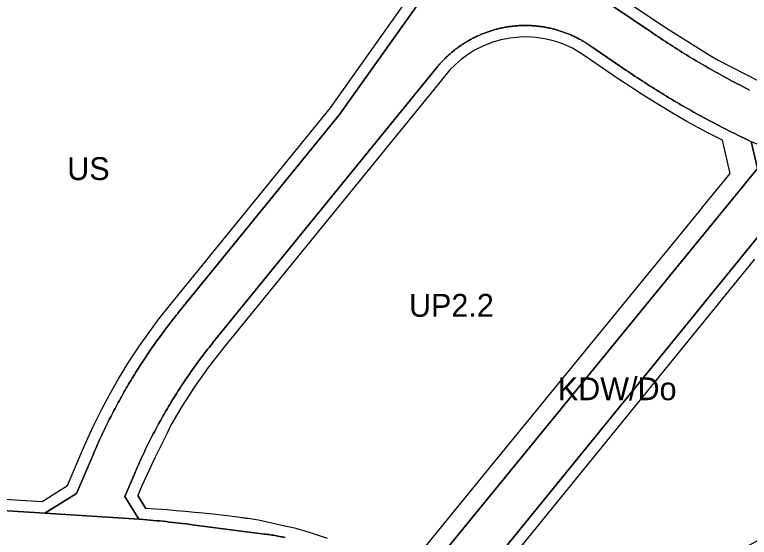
# Model space of a CAD drawing. Extents: x -297746 to -295403, y 27112 to 28877.
# Drawn here: x -296302 to -295980.2, y 28247.4 to 28476.1 of the extents above; entities that cross this region are included whole.
import ezdxf

# ---------------------------------------------------------------- set-up
doc = ezdxf.new("R2010")
doc.units = 0
for name, color, linetype in [('linie_rozgraniczajace', 7, 'Continuous'), ('linie_zabudowy_nieprzekraczalne', 7, 'Continuous'), ('oznaczenia_przeznaczen', 7, 'Continuous')]:
    doc.layers.add(name, color=color, linetype=linetype)

msp = doc.modelspace()

# ---------------------------------------------------------------- linework, layer by layer
at = {"layer": 'linie_rozgraniczajace'}
for points in [[(-295964.466, 28672.993), (-296078.491, 28512.337), (-296077.256, 28505.44), (-296048.43, 28485.757), (-296023.068, 28468.439), (-296022.062, 28467.755), (-296021.054, 28467.074), (-296020.044, 28466.396), (-296019.031, 28465.722), (-296018.016, 28465.051), (-296016.999, 28464.383), (-296015.98, 28463.719), (-296014.959, 28463.058), (-296013.936, 28462.4), (-296012.91, 28461.746), (-296011.882, 28461.095)], [(-296247.672, 28255.329), (-296288.797, 28257.976), (-296274.91, 28266.565), (-296267.737, 28283.472), (-296267.345, 28284.392), (-296266.941, 28285.329), (-296266.533, 28286.263), (-296266.122, 28287.197), (-296265.708, 28288.128), (-296265.289, 28289.058), (-296264.867, 28289.987), (-296264.442, 28290.913), (-296264.012, 28291.839), (-296263.579, 28292.762), (-296263.143, 28293.684), (-296262.703, 28294.603), (-296262.259, 28295.522), (-296261.811, 28296.438), (-296261.361, 28297.353), (-296260.906, 28298.266), (-296260.448, 28299.177), (-296259.986, 28300.086), (-296259.521, 28300.994), (-296259.052, 28301.899), (-296258.58, 28302.803), (-296258.104, 28303.705), (-296257.625, 28304.605), (-296257.142, 28305.503), (-296256.655, 28306.4), (-296256.165, 28307.294), (-296255.672, 28308.186), (-296255.175, 28309.077), (-296254.674, 28309.966), (-296254.17, 28310.852), (-296253.663, 28311.737), (-296253.152, 28312.619), (-296252.638, 28313.5), (-296252.12, 28314.378), (-296251.599, 28315.255), (-296251.074, 28316.129), (-296250.546, 28317.002), (-296250.014, 28317.872), (-296249.479, 28318.74), (-296248.941, 28319.607), (-296248.399, 28320.471), (-296247.854, 28321.333), (-296247.306, 28322.192), (-296246.754, 28323.05), (-296246.199, 28323.905), (-296245.64, 28324.759), (-296245.078, 28325.61), (-296244.513, 28326.458), (-296243.944, 28327.305), (-296243.372, 28328.149), (-296242.797, 28328.991), (-296242.219, 28329.831), (-296241.637, 28330.669), (-296241.052, 28331.504), (-296240.464, 28332.337), (-296239.872, 28333.168), (-296239.277, 28333.996), (-296238.679, 28334.822), (-296238.078, 28335.646), (-296237.473, 28336.467), (-296236.865, 28337.286), (-296236.255, 28338.103), (-296235.64, 28338.917), (-296235.023, 28339.728), (-296234.402, 28340.538), (-296233.779, 28341.345), (-296233.152, 28342.149), (-296232.522, 28342.951), (-296231.889, 28343.75), (-296231.252, 28344.547), (-296230.613, 28345.342), (-296229.97, 28346.134), (-296159.711, 28432.386), (-296112.877, 28498.424)], [(-296112.877, 28498.424), (-296159.711, 28432.386), (-296229.97, 28346.134), (-296230.613, 28345.342), (-296231.252, 28344.547), (-296231.889, 28343.75), (-296232.522, 28342.951), (-296233.152, 28342.149), (-296233.779, 28341.345), (-296234.402, 28340.538), (-296235.023, 28339.728), (-296235.64, 28338.917), (-296236.255, 28338.103), (-296236.865, 28337.286), (-296237.473, 28336.467), (-296238.078, 28335.646), (-296238.679, 28334.822), (-296239.277, 28333.996), (-296239.872, 28333.168), (-296240.464, 28332.337), (-296241.052, 28331.504), (-296241.637, 28330.669), (-296242.219, 28329.831), (-296242.797, 28328.991), (-296243.372, 28328.149), (-296243.944, 28327.305), (-296244.513, 28326.458), (-296245.078, 28325.61), (-296245.64, 28324.759), (-296246.199, 28323.905), (-296246.754, 28323.05), (-296247.306, 28322.192), (-296247.854, 28321.333), (-296248.399, 28320.471), (-296248.941, 28319.607), (-296249.479, 28318.74), (-296250.014, 28317.872), (-296250.546, 28317.002), (-296251.074, 28316.129), (-296251.599, 28315.255), (-296252.12, 28314.378), (-296252.638, 28313.5), (-296253.152, 28312.619), (-296253.663, 28311.737), (-296254.17, 28310.852), (-296254.674, 28309.966), (-296255.175, 28309.077), (-296255.672, 28308.186), (-296256.165, 28307.294), (-296256.655, 28306.4), (-296257.142, 28305.503), (-296257.625, 28304.605), (-296258.104, 28303.705), (-296258.58, 28302.803), (-296259.052, 28301.899), (-296259.521, 28300.994), (-296259.986, 28300.086), (-296260.448, 28299.177), (-296260.906, 28298.266), (-296261.361, 28297.353), (-296261.811, 28296.438), (-296262.259, 28295.522), (-296262.703, 28294.603), (-296263.143, 28293.684), (-296263.579, 28292.762), (-296264.012, 28291.839), (-296264.442, 28290.913), (-296264.867, 28289.987), (-296265.289, 28289.058), (-296265.708, 28288.128), (-296266.122, 28287.197), (-296266.533, 28286.263), (-296266.941, 28285.329), (-296267.345, 28284.392), (-296267.737, 28283.472), (-296274.91, 28266.565), (-296288.797, 28257.976)], [(-296288.797, 28257.976), (-296400.521, 28264.886), (-296431.166, 28266.781), (-296434.768, 28272.351), (-296432.067, 28282.612), (-296419.113, 28316.011), (-296378.717, 28384.494), (-296338.263, 28452.547), (-296327.479, 28466.037), (-296306.95, 28488.333)], [(-295980.107, 28443.17), (-295981.194, 28443.717), (-295982.279, 28444.267), (-295983.363, 28444.821), (-295984.444, 28445.378), (-295985.524, 28445.939), (-295986.601, 28446.503), (-295987.677, 28447.071), (-295988.751, 28447.642), (-295989.823, 28448.217), (-295990.894, 28448.796), (-295991.962, 28449.378), (-295993.028, 28449.963), (-295994.093, 28450.552), (-295995.155, 28451.145), (-295996.216, 28451.741), (-295997.274, 28452.34), (-295998.331, 28452.943), (-295999.386, 28453.55), (-296000.438, 28454.159), (-296001.489, 28454.773), (-296002.538, 28455.39), (-296003.584, 28456.01), (-296004.629, 28456.633), (-296005.671, 28457.261), (-296006.712, 28457.891), (-296007.75, 28458.525), (-296008.786, 28459.162), (-296009.82, 28459.803), (-296010.852, 28460.447), (-296011.882, 28461.095), (-296012.91, 28461.746), (-296013.936, 28462.4), (-296014.959, 28463.058), (-296015.98, 28463.719), (-296016.999, 28464.383), (-296018.016, 28465.051), (-296019.031, 28465.722), (-296020.044, 28466.396), (-296021.054, 28467.074), (-296022.062, 28467.755), (-296023.068, 28468.439), (-296048.43, 28485.757)], [(-296079.255, 28471.419), (-296079.702, 28471.409), (-296080.149, 28471.395), (-296080.596, 28471.376), (-296081.043, 28471.354), (-296081.489, 28471.328), (-296081.935, 28471.298), (-296082.381, 28471.264), (-296082.827, 28471.226), (-296083.272, 28471.184), (-296083.717, 28471.138), (-296084.161, 28471.088), (-296084.605, 28471.034), (-296085.049, 28470.976), (-296085.492, 28470.914), (-296085.934, 28470.849), (-296086.376, 28470.779), (-296086.817, 28470.705), (-296087.257, 28470.627), (-296087.697, 28470.546), (-296088.136, 28470.46), (-296088.574, 28470.371), (-296089.012, 28470.277), (-296089.448, 28470.18), (-296089.884, 28470.079), (-296090.318, 28469.974), (-296090.752, 28469.865), (-296091.185, 28469.752), (-296091.617, 28469.635), (-296092.047, 28469.515), (-296092.477, 28469.39), (-296092.905, 28469.262), (-296093.332, 28469.13), (-296093.759, 28468.994), (-296094.183, 28468.854), (-296094.607, 28468.711), (-296095.029, 28468.564), (-296095.45, 28468.413), (-296095.87, 28468.258), (-296096.288, 28468.099), (-296096.705, 28467.937), (-296097.12, 28467.771), (-296097.534, 28467.601), (-296097.946, 28467.428), (-296098.356, 28467.251), (-296098.766, 28467.07), (-296099.173, 28466.886), (-296099.579, 28466.698), (-296099.983, 28466.506), (-296100.385, 28466.311), (-296100.786, 28466.112), (-296101.184, 28465.909), (-296101.581, 28465.703), (-296101.976, 28465.494), (-296102.37, 28465.281), (-296102.761, 28465.064), (-296103.15, 28464.844), (-296103.538, 28464.621), (-296103.923, 28464.394), (-296104.306, 28464.163), (-296104.687, 28463.929), (-296105.067, 28463.692), (-296105.443, 28463.451), (-296105.818, 28463.208), (-296106.191, 28462.96), (-296106.561, 28462.71), (-296106.929, 28462.456), (-296107.295, 28462.198), (-296107.659, 28461.938), (-296108.02, 28461.674), (-296108.379, 28461.407), (-296108.735, 28461.137), (-296109.089, 28460.864), (-296109.44, 28460.587), (-296109.789, 28460.308), (-296110.136, 28460.025), (-296110.48, 28459.739), (-296110.821, 28459.45), (-296111.16, 28459.158), (-296111.496, 28458.863), (-296111.83, 28458.565), (-296112.161, 28458.264), (-296112.489, 28457.96), (-296112.814, 28457.654), (-296113.137, 28457.344), (-296113.457, 28457.031), (-296113.774, 28456.716), (-296114.088, 28456.398), (-296114.399, 28456.077), (-296114.708, 28455.753), (-296115.013, 28455.426), (-296115.316, 28455.097), (-296115.616, 28454.765), (-296115.912, 28454.431), (-296116.206, 28454.093), (-296116.497, 28453.754), (-296116.784, 28453.411), (-296117.069, 28453.066), (-296117.118, 28453.005), (-296214.464, 28333.502)], [(-296111.83, 28458.565), (-296111.496, 28458.863), (-296111.16, 28459.158), (-296110.821, 28459.45), (-296110.48, 28459.739), (-296110.136, 28460.025), (-296109.789, 28460.308), (-296109.44, 28460.587), (-296109.089, 28460.864), (-296108.735, 28461.137), (-296108.379, 28461.407), (-296108.02, 28461.674), (-296107.659, 28461.938), (-296107.295, 28462.198), (-296106.929, 28462.456), (-296106.561, 28462.71), (-296106.191, 28462.96), (-296105.818, 28463.208), (-296105.443, 28463.451), (-296105.067, 28463.692), (-296104.687, 28463.929), (-296104.306, 28464.163), (-296103.923, 28464.394), (-296103.538, 28464.621), (-296103.15, 28464.844), (-296102.761, 28465.064), (-296102.37, 28465.281), (-296101.976, 28465.494), (-296101.581, 28465.703), (-296101.184, 28465.909), (-296100.786, 28466.112), (-296100.385, 28466.311), (-296099.983, 28466.506), (-296099.579, 28466.698), (-296099.173, 28466.886), (-296098.766, 28467.07), (-296098.356, 28467.251), (-296097.946, 28467.428), (-296097.534, 28467.601), (-296097.12, 28467.771), (-296096.705, 28467.937), (-296096.288, 28468.099), (-296095.87, 28468.258), (-296095.45, 28468.413), (-296095.029, 28468.564), (-296094.607, 28468.711), (-296094.183, 28468.854), (-296093.759, 28468.994), (-296093.332, 28469.13), (-296092.905, 28469.262), (-296092.477, 28469.39), (-296092.047, 28469.515), (-296091.617, 28469.635), (-296091.185, 28469.752), (-296090.752, 28469.865), (-296090.318, 28469.974), (-296089.884, 28470.079), (-296089.448, 28470.18), (-296089.012, 28470.277), (-296088.574, 28470.371), (-296088.136, 28470.46), (-296087.697, 28470.546), (-296087.257, 28470.627), (-296086.817, 28470.705), (-296086.376, 28470.779), (-296085.934, 28470.849), (-296085.492, 28470.914), (-296085.049, 28470.976), (-296084.605, 28471.034), (-296084.161, 28471.088), (-296083.717, 28471.138), (-296083.272, 28471.184), (-296082.827, 28471.226), (-296082.381, 28471.264), (-296081.935, 28471.298), (-296081.489, 28471.328), (-296081.043, 28471.354), (-296080.596, 28471.376), (-296080.149, 28471.395), (-296079.702, 28471.409), (-296079.255, 28471.419), (-296078.808, 28471.425), (-296078.361, 28471.427), (-296077.914, 28471.425), (-296077.466, 28471.419), (-296077.019, 28471.409), (-296076.572, 28471.395), (-296076.126, 28471.377), (-296075.679, 28471.355), (-296075.232, 28471.329), (-296074.786, 28471.299), (-296074.34, 28471.266), (-296073.895, 28471.228), (-296073.449, 28471.186), (-296073.005, 28471.14), (-296072.56, 28471.09), (-296072.116, 28471.036), (-296071.673, 28470.979), (-296071.23, 28470.917), (-296070.787, 28470.851)], [(-296003.528, 28432.915), (-296004.619, 28433.522), (-296005.709, 28434.133), (-296006.796, 28434.748), (-296007.882, 28435.365), (-296008.965, 28435.987), (-296010.047, 28436.611), (-296011.126, 28437.24), (-296012.204, 28437.871), (-296013.279, 28438.506), (-296014.353, 28439.145), (-296015.424, 28439.787), (-296016.493, 28440.432), (-296017.561, 28441.081), (-296018.626, 28441.734), (-296019.689, 28442.389), (-296020.75, 28443.048), (-296021.809, 28443.711), (-296022.865, 28444.377), (-296023.92, 28445.046), (-296024.972, 28445.718), (-296026.023, 28446.394), (-296027.071, 28447.074), (-296028.117, 28447.756), (-296029.16, 28448.442), (-296030.202, 28449.132), (-296031.241, 28449.825), (-296032.278, 28450.521), (-296033.313, 28451.22), (-296034.346, 28451.923), (-296050.158, 28462.719), (-296050.528, 28462.97), (-296050.901, 28463.217), (-296051.276, 28463.461), (-296051.653, 28463.701), (-296052.032, 28463.938), (-296052.413, 28464.172), (-296052.796, 28464.402), (-296053.182, 28464.629), (-296053.569, 28464.853), (-296053.959, 28465.072), (-296054.35, 28465.289), (-296054.743, 28465.502), (-296055.138, 28465.711), (-296055.535, 28465.917), (-296055.934, 28466.119), (-296056.335, 28466.318), (-296056.737, 28466.513), (-296057.141, 28466.705), (-296057.547, 28466.893), (-296057.955, 28467.077), (-296058.364, 28467.258), (-296058.775, 28467.435), (-296059.187, 28467.608), (-296059.601, 28467.777), (-296060.016, 28467.943), (-296060.433, 28468.105), (-296060.851, 28468.264), (-296061.271, 28468.418), (-296061.692, 28468.569), (-296062.114, 28468.716), (-296062.537, 28468.86), (-296062.962, 28468.999), (-296063.388, 28469.135), (-296063.816, 28469.267), (-296064.244, 28469.395), (-296064.674, 28469.519), (-296065.105, 28469.64), (-296065.536, 28469.756), (-296065.969, 28469.869), (-296066.403, 28469.978), (-296066.838, 28470.083), (-296067.273, 28470.184), (-296067.71, 28470.281), (-296068.147, 28470.374), (-296068.585, 28470.464), (-296069.024, 28470.549), (-296069.464, 28470.63), (-296069.904, 28470.708), (-296070.346, 28470.782), (-296070.787, 28470.851), (-296071.23, 28470.917), (-296071.673, 28470.979), (-296072.116, 28471.036), (-296072.56, 28471.09), (-296073.005, 28471.14), (-296073.449, 28471.186), (-296073.895, 28471.228), (-296074.34, 28471.266), (-296074.786, 28471.299), (-296075.232, 28471.329), (-296075.679, 28471.355), (-296076.126, 28471.377), (-296076.572, 28471.395), (-296077.019, 28471.409), (-296077.466, 28471.419), (-296077.914, 28471.425), (-296078.361, 28471.427), (-296078.808, 28471.425), (-296079.255, 28471.419)], [(-296070.787, 28470.851), (-296070.346, 28470.782), (-296069.904, 28470.708), (-296069.464, 28470.63), (-296069.024, 28470.549), (-296068.585, 28470.464), (-296068.147, 28470.374), (-296067.71, 28470.281), (-296067.273, 28470.184), (-296066.838, 28470.083), (-296066.403, 28469.978), (-296065.969, 28469.869), (-296065.536, 28469.756), (-296065.105, 28469.64), (-296064.674, 28469.519), (-296064.244, 28469.395), (-296063.816, 28469.267), (-296063.388, 28469.135), (-296062.962, 28468.999), (-296062.537, 28468.86), (-296062.114, 28468.716), (-296061.692, 28468.569), (-296061.271, 28468.418), (-296060.851, 28468.264), (-296060.433, 28468.105), (-296060.016, 28467.943), (-296059.601, 28467.777), (-296059.187, 28467.608), (-296058.775, 28467.435), (-296058.364, 28467.258), (-296057.955, 28467.077), (-296057.547, 28466.893), (-296057.141, 28466.705), (-296056.737, 28466.513), (-296056.335, 28466.318), (-296055.934, 28466.119), (-296055.535, 28465.917), (-296055.138, 28465.711), (-296054.743, 28465.502), (-296054.35, 28465.289), (-296053.959, 28465.072), (-296053.569, 28464.853), (-296053.182, 28464.629), (-296052.796, 28464.402), (-296052.413, 28464.172), (-296052.032, 28463.938), (-296051.653, 28463.701), (-296051.276, 28463.461), (-296050.901, 28463.217), (-296050.528, 28462.97), (-296050.158, 28462.719), (-296034.346, 28451.923), (-296033.313, 28451.22), (-296032.278, 28450.521), (-296031.241, 28449.825), (-296030.202, 28449.132), (-296029.16, 28448.442), (-296028.117, 28447.756), (-296027.071, 28447.074), (-296026.023, 28446.394), (-296024.972, 28445.718), (-296023.92, 28445.046), (-296022.865, 28444.377), (-296021.809, 28443.711), (-296020.75, 28443.048), (-296019.689, 28442.389), (-296018.626, 28441.734), (-296017.561, 28441.081), (-296016.493, 28440.432), (-296015.424, 28439.787), (-296014.353, 28439.145), (-296013.279, 28438.506), (-296012.204, 28437.871), (-296011.126, 28437.24), (-296010.047, 28436.611), (-296008.965, 28435.987), (-296007.882, 28435.365), (-296006.796, 28434.748), (-296005.709, 28434.133), (-296004.619, 28433.522), (-296003.528, 28432.915), (-296002.435, 28432.311), (-296001.339, 28431.711), (-296000.242, 28431.114), (-295999.143, 28430.521), (-295998.042, 28429.931), (-295996.939, 28429.345), (-295995.835, 28428.762), (-295994.728, 28428.183), (-295993.62, 28427.607), (-295992.509, 28427.035), (-295991.397, 28426.466), (-295990.283, 28425.901), (-295989.168, 28425.34), (-295988.05, 28424.782), (-295986.931, 28424.228), (-295985.81, 28423.677), (-295984.687, 28423.13), (-295983.562, 28422.587), (-295982.436, 28422.047)], [(-296011.882, 28461.095), (-296010.852, 28460.447), (-296009.82, 28459.803), (-296008.786, 28459.162), (-296007.75, 28458.525), (-296006.712, 28457.891), (-296005.671, 28457.261), (-296004.629, 28456.633), (-296003.584, 28456.01), (-296002.538, 28455.39), (-296001.489, 28454.773), (-296000.438, 28454.159), (-295999.386, 28453.55), (-295998.331, 28452.943), (-295997.274, 28452.34), (-295996.216, 28451.741), (-295995.155, 28451.145), (-295994.093, 28450.552), (-295993.028, 28449.963), (-295991.962, 28449.378), (-295990.894, 28448.796), (-295989.823, 28448.217), (-295988.751, 28447.642), (-295987.677, 28447.071), (-295986.601, 28446.503), (-295985.524, 28445.939), (-295984.444, 28445.378), (-295983.363, 28444.821), (-295982.279, 28444.267), (-295981.194, 28443.717), (-295980.107, 28443.17)], [(-296237.058, 28254.346), (-296238.479, 28254.491), (-296239.9, 28254.632), (-296241.322, 28254.768), (-296242.744, 28254.901), (-296244.166, 28255.03), (-296245.589, 28255.154), (-296247.012, 28255.275), (-296247.672, 28255.329), (-296253.74, 28265.256), (-296249.325, 28275.661), (-296249.265, 28275.802), (-296248.88, 28276.703), (-296248.491, 28277.603), (-296248.099, 28278.5), (-296247.703, 28279.397), (-296247.303, 28280.291), (-296246.9, 28281.184), (-296246.493, 28282.075), (-296246.082, 28282.965), (-296245.668, 28283.853), (-296245.25, 28284.739), (-296244.828, 28285.623), (-296244.403, 28286.506), (-296243.974, 28287.387), (-296243.542, 28288.266), (-296243.106, 28289.144), (-296242.667, 28290.02), (-296242.224, 28290.893), (-296241.777, 28291.766), (-296241.327, 28292.636), (-296240.873, 28293.504), (-296240.416, 28294.371), (-296239.955, 28295.235), (-296239.491, 28296.098), (-296239.023, 28296.959), (-296238.551, 28297.818), (-296238.076, 28298.675), (-296237.598, 28299.53), (-296237.116, 28300.383), (-296236.631, 28301.234), (-296236.142, 28302.084), (-296235.65, 28302.931), (-296235.154, 28303.776), (-296234.655, 28304.619), (-296234.152, 28305.46), (-296233.646, 28306.299), (-296233.137, 28307.136), (-296232.624, 28307.971), (-296232.108, 28308.803), (-296231.588, 28309.634), (-296231.065, 28310.463), (-296230.539, 28311.289), (-296230.009, 28312.113), (-296229.476, 28312.935), (-296228.939, 28313.755), (-296228.399, 28314.573), (-296227.856, 28315.388), (-296227.309, 28316.201), (-296226.76, 28317.012), (-296226.207, 28317.821), (-296225.65, 28318.628), (-296225.09, 28319.432), (-296224.527, 28320.234), (-296223.961, 28321.033), (-296223.392, 28321.83), (-296222.819, 28322.625), (-296222.243, 28323.418), (-296221.663, 28324.208), (-296221.081, 28324.996), (-296220.495, 28325.782), (-296219.906, 28326.565), (-296219.314, 28327.345), (-296218.719, 28328.124), (-296218.121, 28328.899), (-296217.519, 28329.673), (-296216.914, 28330.444), (-296216.306, 28331.212), (-296215.695, 28331.978), (-296215.081, 28332.741), (-296214.464, 28333.502), (-296117.118, 28453.005), (-296117.069, 28453.066), (-296116.784, 28453.411), (-296116.497, 28453.754), (-296116.206, 28454.093), (-296115.912, 28454.431), (-296115.616, 28454.765), (-296115.316, 28455.097), (-296115.013, 28455.426), (-296114.708, 28455.753), (-296114.399, 28456.077), (-296114.088, 28456.398), (-296113.774, 28456.716), (-296113.457, 28457.031), (-296113.137, 28457.344), (-296112.814, 28457.654), (-296112.489, 28457.96), (-296112.161, 28458.264), (-296111.83, 28458.565)], [(-295980.178, 28420.978), (-295981.308, 28421.511), (-295982.436, 28422.047), (-295983.562, 28422.587), (-295984.687, 28423.13), (-295985.81, 28423.677), (-295986.931, 28424.228), (-295988.05, 28424.782), (-295989.168, 28425.34), (-295990.283, 28425.901), (-295991.397, 28426.466), (-295992.509, 28427.035), (-295993.62, 28427.607), (-295994.728, 28428.183), (-295995.835, 28428.762), (-295996.939, 28429.345), (-295998.042, 28429.931), (-295999.143, 28430.521), (-296000.242, 28431.114), (-296001.339, 28431.711), (-296002.435, 28432.311), (-296003.528, 28432.915)], [(-295982.436, 28422.047), (-295981.308, 28421.511), (-295980.178, 28420.978), (-295979.492, 28420.656), (-295976.708, 28408.799), (-296124.921, 28227.519), (-296138.842, 28226.292)], [(-295801.022, 28344.329), (-296090.869, 28181.936), (-296109.613, 28199.497), (-296110.601, 28214.092), (-295958.614, 28400.965)], [(-296214.464, 28333.502), (-296215.081, 28332.741), (-296215.695, 28331.978), (-296216.306, 28331.212), (-296216.914, 28330.444), (-296217.519, 28329.673), (-296218.121, 28328.899), (-296218.719, 28328.124), (-296219.314, 28327.345), (-296219.906, 28326.565), (-296220.495, 28325.782), (-296221.081, 28324.996), (-296221.663, 28324.208), (-296222.243, 28323.418), (-296222.819, 28322.625), (-296223.392, 28321.83), (-296223.961, 28321.033), (-296224.527, 28320.234), (-296225.09, 28319.432), (-296225.65, 28318.628), (-296226.207, 28317.821), (-296226.76, 28317.012), (-296227.309, 28316.201), (-296227.856, 28315.388), (-296228.399, 28314.573), (-296228.939, 28313.755), (-296229.476, 28312.935), (-296230.009, 28312.113), (-296230.539, 28311.289), (-296231.065, 28310.463), (-296231.588, 28309.634), (-296232.108, 28308.803), (-296232.624, 28307.971), (-296233.137, 28307.136), (-296233.646, 28306.299), (-296234.152, 28305.46), (-296234.655, 28304.619), (-296235.154, 28303.776), (-296235.65, 28302.931), (-296236.142, 28302.084), (-296236.631, 28301.234), (-296237.116, 28300.383), (-296237.598, 28299.53), (-296238.076, 28298.675), (-296238.551, 28297.818), (-296239.023, 28296.959), (-296239.491, 28296.098), (-296239.955, 28295.235), (-296240.416, 28294.371), (-296240.873, 28293.504), (-296241.327, 28292.636), (-296241.777, 28291.766), (-296242.224, 28290.893), (-296242.667, 28290.02), (-296243.106, 28289.144), (-296243.542, 28288.266), (-296243.974, 28287.387), (-296244.403, 28286.506), (-296244.828, 28285.623), (-296245.25, 28284.739), (-296245.668, 28283.853), (-296246.082, 28282.965), (-296246.493, 28282.075), (-296246.9, 28281.184), (-296247.303, 28280.291), (-296247.703, 28279.397), (-296248.099, 28278.5), (-296248.491, 28277.603), (-296248.88, 28276.703), (-296249.265, 28275.802), (-296249.325, 28275.661), (-296253.74, 28265.256), (-296247.672, 28255.329)], [(-296400.521, 28264.886), (-296288.797, 28257.976), (-296247.672, 28255.329), (-296247.012, 28255.275), (-296245.589, 28255.154), (-296244.166, 28255.03), (-296242.744, 28254.901), (-296241.322, 28254.768), (-296239.9, 28254.632), (-296238.479, 28254.491), (-296237.058, 28254.346), (-296235.637, 28254.198), (-296234.217, 28254.045), (-296232.797, 28253.889), (-296231.378, 28253.728), (-296229.959, 28253.564), (-296228.541, 28253.395), (-296227.123, 28253.223), (-296225.706, 28253.047), (-296224.289, 28252.866), (-296192.624, 28248.791), (-296191.999, 28248.708), (-296191.341, 28248.618), (-296190.685, 28248.523), (-296190.029, 28248.425), (-296189.373, 28248.323), (-296188.719, 28248.217), (-296188.065, 28248.106), (-296187.411, 28247.992), (-296186.758, 28247.874), (-296186.106, 28247.752), (-296185.455, 28247.626), (-296184.805, 28247.496), (-296184.155, 28247.362), (-296183.506, 28247.225)], [(-296183.506, 28247.225), (-296184.155, 28247.362), (-296184.805, 28247.496), (-296185.455, 28247.626), (-296186.106, 28247.752), (-296186.758, 28247.874), (-296187.411, 28247.992), (-296188.065, 28248.106), (-296188.719, 28248.217), (-296189.373, 28248.323), (-296190.029, 28248.425), (-296190.685, 28248.523), (-296191.341, 28248.618), (-296191.999, 28248.708), (-296192.624, 28248.791), (-296224.289, 28252.866), (-296225.706, 28253.047), (-296227.123, 28253.223), (-296228.541, 28253.395), (-296229.959, 28253.564), (-296231.378, 28253.728), (-296232.797, 28253.889), (-296234.217, 28254.045), (-296235.637, 28254.198), (-296237.058, 28254.346)]]:
    msp.add_lwpolyline(points, dxfattribs=at)
msp.add_lwpolyline([(-296109.613, 28199.497), (-296138.842, 28226.292), (-296124.921, 28227.519), (-295976.708, 28408.799), (-295979.492, 28420.656), (-295942.793, 28405.637), (-295958.614, 28400.965), (-296110.601, 28214.092)], close=True, dxfattribs=at)
at = {"layer": 'linie_zabudowy_nieprzekraczalne'}
for points in [[(-295961.128, 28669.056), (-296073.197, 28511.155), (-296072.701, 28508.388), (-296039.661, 28485.828), (-296015.803, 28469.784), (-296015.794, 28469.796), (-295997.343, 28458.313), (-295993.947, 28456.199), (-295976.166, 28447.237), (-295950.713, 28453.425), (-295935.343, 28472.599), (-295919.148, 28492.8), (-295839.728, 28590.205), (-295810.009, 28626.655)], [(-296413.159, 28270.416), (-296410.576, 28270.359), (-296408.157, 28270.284), (-296404.116, 28270.108), (-296400.188, 28269.877), (-296290.072, 28263.067), (-296278.889, 28269.983), (-296272.337, 28285.427), (-296270.012, 28290.744), (-296267.355, 28296.462), (-296263.995, 28303.222), (-296260.355, 28310.046), (-296256.535, 28316.733), (-296251.981, 28324.158), (-296247.403, 28331.111), (-296243.646, 28336.483), (-296239.133, 28342.583), (-296233.835, 28349.305), (-296163.69, 28435.416), (-296118.009, 28499.829)], [(-296129.893, 28233.813), (-296098.245, 28272.522), (-296002.041, 28390.189), (-296000.534, 28392.032), (-295988.564, 28406.673), (-295991.963, 28421.152), (-295999.008, 28424.786), (-296007.547, 28429.435), (-296013.664, 28432.935), (-296021.044, 28437.355), (-296027.22, 28441.224), (-296031.414, 28443.944), (-296034.947, 28446.294), (-296037.511, 28447.964), (-296040.02, 28449.709), (-296052.974, 28458.592), (-296057.756, 28461.44), (-296060.372, 28462.682), (-296063.503, 28463.909), (-296066.641, 28464.879), (-296070.016, 28465.651), (-296073.541, 28466.171), (-296077.411, 28466.419), (-296080.575, 28466.374), (-296085.049, 28465.927), (-296089.132, 28465.118), (-296093.006, 28463.975), (-296096.936, 28462.411), (-296100.556, 28460.568), (-296103.302, 28458.877), (-296106.351, 28456.656), (-296108.997, 28454.379), (-296111.418, 28451.949), (-296113.239, 28449.849), (-296210.584, 28330.346), (-296217.346, 28321.636), (-296223.319, 28313.174), (-296228.792, 28304.654), (-296232.232, 28298.852), (-296232.931, 28297.624), (-296233.429, 28296.666), (-296235.311, 28292.996), (-296240.497, 28282.461), (-296243.44, 28276.185), (-296244.296, 28274.314), (-296246.286, 28269.885), (-296248.13, 28265.672), (-296244.724, 28260.1), (-296240.252, 28259.815), (-296235.283, 28259.458), (-296231.273, 28259.138), (-296227.15, 28258.779), (-296223.333, 28258.421), (-296219.512, 28258.036), (-296215.202, 28257.571), (-296210.205, 28256.991), (-296205.659, 28256.425), (-296202.04, 28255.949), (-296198.956, 28255.524)], [(-295978.031, 28369.166), (-296073.928, 28251.257), (-296105.477, 28212.467), (-296104.755, 28201.802), (-296088.01, 28186.113), (-296078.522, 28177.224), (-296060.296, 28160.149), (-296037.557, 28172.759)], [(-296244.724, 28260.1), (-296248.13, 28265.672)], [(-296202.716, 28256.057), (-296200.836, 28255.794), (-296198.956, 28255.524), (-296197.078, 28255.247), (-296195.201, 28254.963), (-296182.457, 28252.116), (-296180.681, 28251.719), (-296178.911, 28251.294), (-296177.147, 28250.84), (-296175.392, 28250.359)], [(-296175.392, 28250.359), (-296172.164, 28249.377), (-296168.604, 28248.177), (-296165.207, 28246.912)]]:
    msp.add_lwpolyline(points, dxfattribs=at)

# ---------------------------------------------------------------- texts
at = {"layer": 'oznaczenia_przeznaczen'}
for s, p in [('US', (-296279.033, 28403.761)), ('UP2.2', (-296129.323, 28343.903)), ('KDW/Do', (-296064.123, 28307.378))]:
    msp.add_text(s, height=10, dxfattribs=at).set_placement(p)

doc.saveas('drawing.dxf')
